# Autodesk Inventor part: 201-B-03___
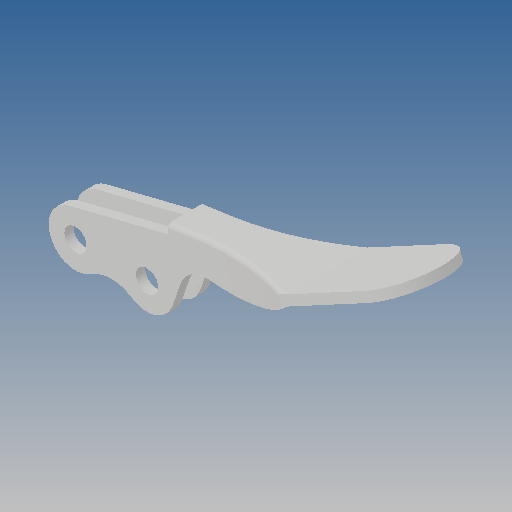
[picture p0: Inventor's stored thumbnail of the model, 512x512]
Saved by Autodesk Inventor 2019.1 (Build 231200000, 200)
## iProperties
Created: 2010-06
Part Number: 201-B-03___
Material: Ogólny
Document SubType Name: Modeling
Designer: CADENGINEERING4
Density: 1 g/cm^3
Appearance: Domyślna
Author: CADENGINEERING4
Revision Number: ANY
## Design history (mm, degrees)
feature "NONE"
node "Bryła1"
